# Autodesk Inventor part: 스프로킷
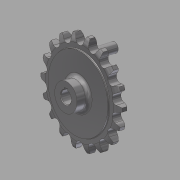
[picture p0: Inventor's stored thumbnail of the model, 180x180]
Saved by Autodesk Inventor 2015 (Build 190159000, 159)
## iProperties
Created: 2016-03
Part Number: 스프로킷
Material: 강철, 탄소
Document SubType Name: Modeling
Designer: mduedu
Density: 7.87 g/cm^3
Mass: 309.171 g
Surface Area: 126.546 cm^2
Volume: 39.2847 cm^3
Appearance: 반광택
Author: mduedu
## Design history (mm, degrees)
sketch "스케치1"
  geometry: L1 (0, 5)-(29.5, 5); L2 (29.5, 5)-(29.5, 4.1); L3 (30, 3.6)-(33.625, 3.6); L4 (40, 2)-(40, 0); L5 (40, 0)-(0, 0); L6 (0, 0)-(0, 5); L7 (0, -5)-(29.5, -5); L8 (29.5, -5)-(29.5, -4.1); L9 (30, -3.6)-(33.625, -3.6); L10 (40, -2)-(40, 0); L11 (0, 0)-(0, -5); A1 r 13.5 centre (33.625, -9.9) between (40, 2) and (33.625, 3.6); A2 r 13.5 centre (33.625, 9.9) between (33.625, -3.6) and (40, -2); A3 r 0.5 centre (30, 4.1) between (29.5, 4.1) and (30, 3.6); A4 r 0.5 centre (30, -4.1) between (30, -3.6) and (29.5, -4.1); 2 further points
  constraints: 22 end point, 8 point on circle, 6 symmetric about line, 5 tangent, 4 centre point, 4 parallel, 4 point on line, 1 equal radius, 1 horizontal, 1 perpendicular, 1 other
  dimensions: "d0" = 80 diameter of L4 L6; "d2" = 59 diameter of L2 L6; "d3" = 1.6 vertical distance of L4.start L3.end; "d4" = 3.6 distance from line of L4.end L3; "d5" = 5 distance between parallel lines of L5 L1; "d6" = 13.5 radius of A1; "d15" = 0.5 radius of A3
revolve "회전1" sketch "스케치1" stored, may be unused: angle "d7" = 90 deg
sketch "스케치2" dims "d8" = 65.2, "d11" = 80
  geometry: L1 (0, 0)-(0, 32.6); A1 r 36.57 centre (0, 0) between (-16.231, 32.771) and (0, 36.57); A2 r 3.97 centre (0, 36.57) between (-3.866, 35.665) and (0, 32.6); A3 r 12.7 centre (-16.231, 32.771) between (-3.866, 35.665) and (-5.534, 39.615); A4 r 12.7 centre (16.231, 32.771) between (5.534, 39.615) and (3.866, 35.665); A5 r 3.97 centre (0, 36.57) between (0, 32.6) and (3.866, 35.665); A6 r 40 centre (0, 0) between (5.534, 39.615) and (-5.534, 39.615); 2 further points
  constraints: 12 point on circle, 6 centre point, 4 coincident, 3 symmetric about line, 2 end point, 1 point on line, 1 tangent, 1 vertical, 1 vertical alignment, 7 other
  dimensions: "d10" = 73.14 diameter of A1; "d12" = 12.7 radius of A3
extrude "돌출1" cut sketch "스케치2" stored distance "d13" = 10; taper "d14" = 0 deg
sketch "스케치3"
  geometry: C1 r 11 at (0, 0); 1 further point
  constraints: 1 centre point, 1 coincident
  dimensions: "d19" = 22 diameter of C1
extrude "돌출2" join sketch "스케치3" distance "d20" = 10; taper "d21" = 0 deg
fillet "모깎기1" dims "d22" = 3
sketch "스케치4"
  geometry: L1 (-1.5, 0)-(1.5, 0); L2 (1.5, 0)-(1.5, 6.4); L3 (1.5, 6.4)-(-1.5, 6.4); L4 (-1.5, 6.4)-(-1.5, 0); C1 r 5 at (0, 0); 2 further points
  constraints: 8 end point, 2 coincident, 2 parallel, 1 centre point, 1 horizontal, 1 midpoint, 1 perpendicular
  dimensions: "d23" = 10 diameter of C1; "d25" = 3 distance of L2.end L3.end; "d26" = 6.4 distance of L1.end L2.end
extrude "돌출3" cut sketch "스케치4" stored distance "d27" = 8; taper "d28" = 0 deg
chamfer "모따기1" distance "d29" = 0.5; stored, may be unused: second distance "d30" = 2, angle "d31" = 45 deg
sketch "스케치5" dims "d33" = 48
  geometry: C1 r 4 at (0, 24); 2 further points
  constraints: 2 vertical alignment, 1 centre point, 1 coincident, 2 other
  dimensions: "d32" = 8 diameter of C1
extrude "돌출4" join sketch "스케치5" distance "d34" = 20; taper "d35" = 0 deg
fillet "모깎기2" dims "d36" = 1
hole "구멍1" diameter "d39" = 3.242; stored, may be unused: countersink angle "d43" = 90 deg, drill point angle "d45" = 118 deg; dims "d40" = 8, "d41" = 4, "d42" = 2, "d44" = 10, "d46" = 10, "d47" = 10
node "솔리드1"
pattern_circular "원형 패턴1" dims angle "d17" = 360 deg
